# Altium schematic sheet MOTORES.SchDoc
size A4
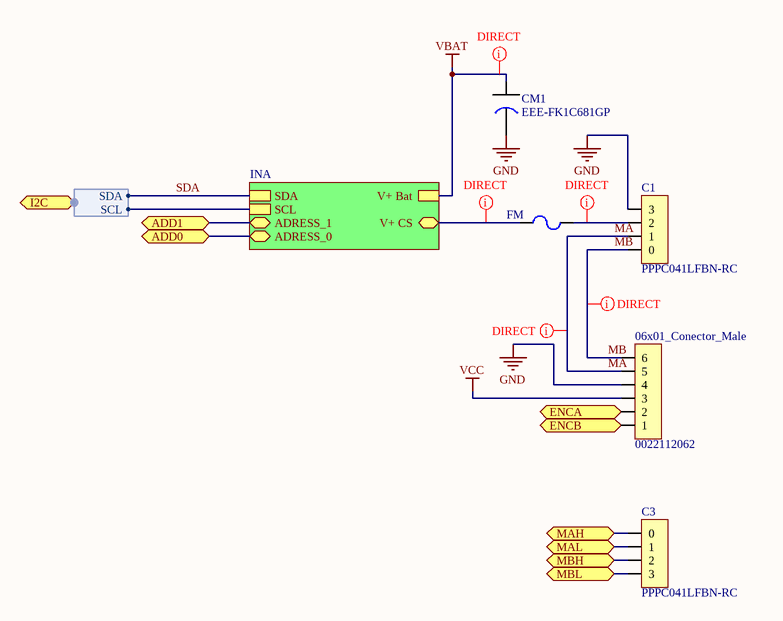
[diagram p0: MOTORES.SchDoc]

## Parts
06x01_Conector_Male  0022112062  [06x01_Conector_Male]
C1  PPPC041LFBN-RC  [04x01_Conector_Female]
C3  PPPC041LFBN-RC  [04x01_Conector_Female]
CM1  EEE-FK1C681GP  [EEE-FK1C681GP]
FM  MF-MSMF250/16X  [RESC4632X16N]  (value not drawn)

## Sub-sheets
INA = INA220.SchDoc: V+ Bat, SDA, SCL, ADRESS_1, ADRESS_0, V+ CS

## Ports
ADD0, ADD1, ENCA, ENCB, I2C (harness I2C), MAH, MAL, MBH, MBL

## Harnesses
I2C: SDA, SCL

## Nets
GND: 06x01_Conector_Male.4 C1.3 CM1.2
VBAT: CM1.1 ; sheet INA/V+ Bat
VCC: 06x01_Conector_Male.3
ADD0: port ADD0, sheet INA/ADRESS_0
ADD1: port ADD1, sheet INA/ADRESS_1
ENCA: 06x01_Conector_Male.2 ; port ENCA
ENCB: 06x01_Conector_Male.1 ; port ENCB
MA: 06x01_Conector_Male.5 C1.1
MAH: C3.0 ; port MAH
MAL: C3.1 ; port MAL
MB: 06x01_Conector_Male.6 C1.0
MBH: C3.2 ; port MBH
MBL: C3.3 ; port MBL
SDA: sheet INA/SDA, port I2C.SDA
NetC1_2: C1.2 FM.1
NetFM_2: FM.2 ; sheet INA/V+ CS
(unnamed): sheet INA/SCL, port I2C.SCL

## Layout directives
net class DIRECT: MA, MB, NetC1_2, NetFM_2, VBAT

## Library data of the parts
06x01_Conector_Male = 06x01_Conector_Male: CONN HEADER 6POS .100 VERT GOLD
C1 C3 = 04x01_Conector_Female-SCH: 4 Position Header Connector 0.100" (2.54mm) Through Hole Gold
CM1 = CAP AL 680UF/16V: Aluminum Electrolytic Capacitors - SMD Al Lytic Cap SMT FK Series 105C
FM = MF-MSMF250/16X-01.A.1: PTC RESETTABLE .30A 30V 1812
